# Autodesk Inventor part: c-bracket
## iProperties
Author: Elise Moss
Length Units: 11272
Angle Units: 11279
Time Units: 11290
Mass Units: 11286
Shininess: 3
Angle Display Precision: 2
Document Length Units: 11272
Document Angle Units: 11286
Document Time Units: 11279
Document Mass Units: 11290
Document Length Units Precision: 3
Document Angle Units Precision: 0
Compacted: False
PropertySet Name: _Private Model Information
Created: 2001-09
Part Number: c-bracket
Document SubType Name: Modeling
Designer: Elise Moss
Control State: 0
Master: False
Checked Out: False
PropertySet Name: Design Tracking Control
Density: 0.0
Volumn: 0.0
Area: 0.0
PropertySet Name: Model Information
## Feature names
1. Extrusion1
2. Extrusion2
3. Extrusion3
4. Extrusion4
5. Extrusion5
6. Extrusion6
7. Mirror1
8. Fillet1
9. Hole1
